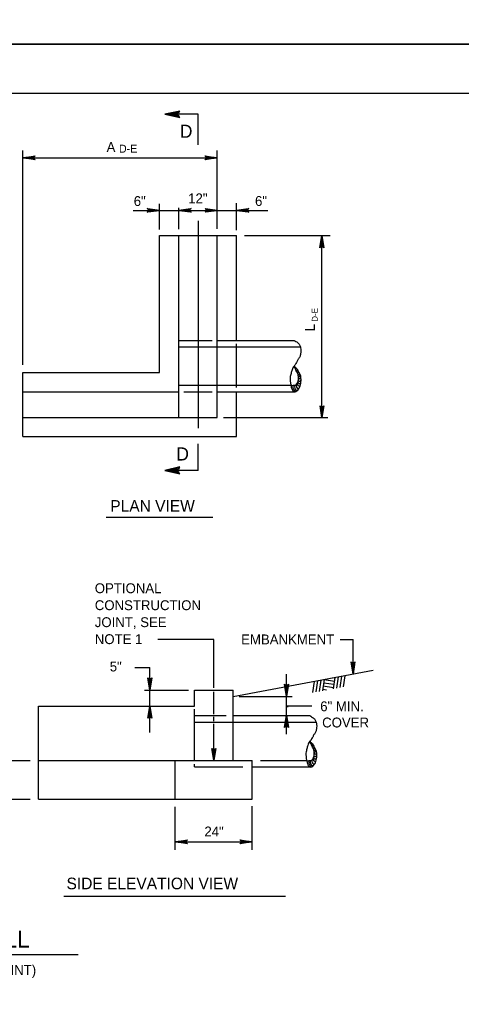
# Model space of a CAD drawing. Extents: x 638877 to 639960, y 297341 to 299123.
# Drawn here: x 639059.3 to 639193.8, y 298239.6 to 298536.8 of the extents above; entities that cross this region are included whole.
import ezdxf

# ---------------------------------------------------------------- set-up
doc = ezdxf.new("R2010")
doc.units = 0
for name, color, linetype in [('1', 7, 'Continuous'), ('2', 7, 'Continuous'), ('3', 7, 'Continuous'), ('PLT-BNDY', 7, 'Continuous')]:
    doc.layers.add(name, color=color, linetype=linetype)

msp = doc.modelspace()

# ---------------------------------------------------------------- linework, layer by layer
at = {"layer": '1'}
for p, q in [((639703.19, 298514.28), (638917.19, 298514.28)), ((639113.62, 298498.68), (639113.62, 298507.99)), ((639113.62, 298475.64), (639113.62, 298412.62)), ((639113.62, 298399.73), (639113.62, 298407.86)), ((639118.42, 298333.63), (639118.42, 298348.41)), ((639156.27, 298336.99), (639155.76, 298333.57)), ((639157.29, 298337.18), (639156.78, 298333.76)), ((639158.32, 298337.37), (639157.8, 298333.95)), ((639148.95, 298335.63), (639148.44, 298332.23)), ((639149.98, 298335.82), (639149.46, 298332.42)), ((639151, 298336.01), (639150.49, 298332.61)), ((639152.02, 298336.2), (639151.51, 298332.79)), ((639154.81, 298333.69), (639151.71, 298334.16)), ((639154.96, 298334.66), (639151.86, 298335.13)), ((639155.11, 298335.63), (639152.01, 298336.1)), ((639155.25, 298336.6), (639154.67, 298336.69)), ((639155.25, 298336.8), (639154.74, 298333.39)), ((639118.42, 298325.7), (639118.42, 298332.47)), ((639152.71, 298333.01), (639151.57, 298333.18)), ((639118.42, 298323.58), (639118.42, 298324.9)), ((639118.42, 298311.57), (639118.42, 298322.7))]:
    msp.add_line(p, q, dxfattribs=at)
at = {"layer": '2'}
for p, q in [((639113.62, 298507.99), (639103.48, 298507.99)), ((639060.32, 298431.85), (639060.32, 298496.98)), ((639060.32, 298494.76), (639119.47, 298494.76)), ((639119.47, 298473.15), (639119.47, 298496.98)), ((639101.92, 298472.96), (639101.92, 298480.79)), ((639125.32, 298472.81), (639125.32, 298480.94)), ((639093.88, 298478.8), (639107.77, 298478.8)), ((639107.77, 298473.1), (639107.77, 298479.57)), ((639107.77, 298478.8), (639119.47, 298478.8)), ((639119.47, 298478.8), (639134.9, 298478.8)), ((639101.92, 298429.54), (639101.92, 298471.14)), ((639101.92, 298471.14), (639125.32, 298471.14)), ((639107.77, 298415.89), (639107.77, 298471.14)), ((639119.47, 298415.89), (639119.47, 298471.14)), ((639125.32, 298439.29), (639125.32, 298471.14)), ((639127.8, 298471.14), (639153.78, 298471.14)), ((639151.32, 298415.89), (639151.32, 298471.14)), ((639107.77, 298439.29), (639117.93, 298439.29)), ((639119.47, 298439.29), (639142.87, 298439.29)), ((639125.32, 298424.96), (639125.32, 298438.2)), ((639107.77, 298437.34), (639144.61, 298437.34)), ((639060.32, 298429.54), (639101.92, 298429.54)), ((639060.32, 298410.04), (639060.32, 298429.54)), ((639060.32, 298423.69), (639107.77, 298423.69)), ((639107.77, 298425.64), (639141.85, 298425.64)), ((639109.32, 298423.69), (639117.93, 298423.69)), ((639119.47, 298423.69), (639142.87, 298423.69)), ((639125.32, 298410.04), (639125.32, 298423.69)), ((639060.32, 298415.89), (639119.47, 298415.89)), ((639121.37, 298415.89), (639153.12, 298415.89)), ((639060.32, 298410.04), (639125.32, 298410.04)), ((639113.62, 298399.73), (639103.48, 298399.73)), ((639118.42, 298348.41), (639101.37, 298348.41)), ((639156.86, 298348.41), (639160.78, 298348.41)), ((639160.78, 298337.86), (639160.78, 298348.41)), ((639094.44, 298339.9), (639098.96, 298339.9)), ((639098.96, 298328.14), (639098.96, 298339.9)), ((639124.27, 298331.07), (639166.89, 298339)), ((639140.55, 298331.07), (639140.55, 298337.83)), ((639097.37, 298333.02), (639110.72, 298333.02)), ((639112.57, 298333.02), (639124.27, 298333.02)), ((639112.57, 298328.14), (639112.57, 298333.02)), ((639124.27, 298311.57), (639124.27, 298333.02)), ((639126.16, 298331.07), (639142.22, 298331.07)), ((639140.55, 298325.35), (639140.55, 298331.07)), ((639065.12, 298299.87), (639065.12, 298328.14)), ((639065.12, 298328.14), (639112.57, 298328.14)), ((639098.96, 298320.15), (639098.96, 298328.14)), ((639140.55, 298328.21), (639148.24, 298328.21)), ((639112.57, 298311.57), (639112.57, 298327.18)), ((639112.57, 298325.22), (639122.17, 298325.22)), ((639124.27, 298325.22), (639147.67, 298325.22)), ((639140.55, 298319.63), (639140.55, 298325.35)), ((639112.57, 298323.27), (639149.41, 298323.27)), ((639010.52, 298311.57), (639062.52, 298311.57)), ((639065.12, 298311.57), (639130.12, 298311.57)), ((639106.72, 298299.87), (639106.72, 298311.57)), ((639112.57, 298309.62), (639112.57, 298310.5)), ((639130.12, 298299.87), (639130.12, 298311.57)), ((639132.63, 298311.57), (639146.65, 298311.57)), ((639112.57, 298309.62), (639127.28, 298309.62)), ((639130.12, 298309.62), (639147.67, 298309.62)), ((639010.52, 298299.87), (639062.52, 298299.87)), ((639065.12, 298299.87), (639130.12, 298299.87)), ((639106.72, 298284.49), (639106.72, 298297.48)), ((639130.12, 298284.49), (639130.12, 298297.76)), ((639106.72, 298286.88), (639130.12, 298286.88))]:
    msp.add_line(p, q, dxfattribs=at)
for points in [[(639107.84, 298508.72), (639107.68, 298508.3), (639103.48, 298507.99), (639107.84, 298508.72), (639108.06, 298508.97), (639103.48, 298507.99), (639107.67, 298507.71), (639107.83, 298507.3), (639103.48, 298507.99), (639108.06, 298507.02), (639107.83, 298507.3)], [(639063.86, 298494.32), (639063.73, 298494.57), (639060.32, 298494.76), (639063.86, 298494.32), (639064.04, 298494.16), (639060.32, 298494.76), (639063.73, 298494.93), (639063.85, 298495.18), (639060.32, 298494.76), (639064.04, 298495.35), (639063.85, 298495.18)], [(639115.93, 298495.21), (639116.06, 298494.95), (639119.47, 298494.76), (639115.93, 298495.21), (639115.75, 298495.36), (639119.47, 298494.76), (639116.06, 298494.59), (639115.94, 298494.34), (639119.47, 298494.76), (639115.75, 298494.17), (639115.94, 298494.34)], [(639098.38, 298479.25), (639098.51, 298478.99), (639101.92, 298478.8), (639098.38, 298479.25), (639098.2, 298479.4), (639101.92, 298478.8), (639098.51, 298478.63), (639098.39, 298478.38), (639101.92, 298478.8), (639098.2, 298478.21), (639098.39, 298478.38)], [(639111.31, 298478.36), (639111.18, 298478.62), (639107.77, 298478.8), (639111.31, 298478.36), (639111.49, 298478.2), (639107.77, 298478.8), (639111.18, 298478.97), (639111.3, 298479.22), (639107.77, 298478.8), (639111.49, 298479.4), (639111.3, 298479.22)], [(639115.93, 298479.25), (639116.06, 298478.99), (639119.47, 298478.8), (639115.93, 298479.25), (639115.75, 298479.4), (639119.47, 298478.8), (639116.06, 298478.63), (639115.94, 298478.38), (639119.47, 298478.8), (639115.75, 298478.21), (639115.94, 298478.38)], [(639128.86, 298478.36), (639128.73, 298478.62), (639125.32, 298478.8), (639128.86, 298478.36), (639129.04, 298478.2), (639125.32, 298478.8), (639128.73, 298478.97), (639128.85, 298479.22), (639125.32, 298478.8), (639129.04, 298479.4), (639128.85, 298479.22)], [(639150.88, 298467.6), (639151.13, 298467.74), (639151.32, 298471.14), (639150.88, 298467.6), (639150.72, 298467.42), (639151.32, 298471.14), (639151.49, 298467.74), (639151.74, 298467.61), (639151.32, 298471.14), (639151.91, 298467.42), (639151.74, 298467.61)], [(639151.74, 298419.2), (639151.5, 298419.08), (639151.32, 298415.89), (639151.74, 298419.2), (639151.88, 298419.37), (639151.32, 298415.89), (639151.16, 298419.07), (639150.93, 298419.19), (639151.32, 298415.89), (639150.77, 298419.37), (639150.93, 298419.19)], [(639107.84, 298400.54), (639107.68, 298400.08), (639103.48, 298399.73), (639107.84, 298400.54), (639108.06, 298400.81), (639103.48, 298399.73), (639107.67, 298399.43), (639107.83, 298398.98), (639103.48, 298399.73), (639108.06, 298398.67), (639107.83, 298398.98)], [(639161.23, 298341.4), (639160.97, 298341.27), (639160.78, 298337.86), (639161.23, 298341.4), (639161.38, 298341.58), (639160.78, 298337.86), (639160.61, 298341.26), (639160.36, 298341.39), (639160.78, 298337.86), (639160.19, 298341.58), (639160.36, 298341.39)], [(639099.41, 298336.56), (639099.15, 298336.42), (639098.96, 298333.02), (639099.41, 298336.56), (639099.56, 298336.74), (639098.96, 298333.02), (639098.79, 298336.42), (639098.54, 298336.55), (639098.96, 298333.02), (639098.37, 298336.74), (639098.54, 298336.55)], [(639141, 298334.61), (639140.74, 298334.47), (639140.55, 298331.07), (639141, 298334.61), (639141.15, 298334.79), (639140.55, 298331.07), (639140.38, 298334.47), (639140.13, 298334.6), (639140.55, 298331.07), (639139.96, 298334.79), (639140.13, 298334.6)], [(639098.52, 298324.6), (639098.78, 298324.73), (639098.96, 298328.14), (639098.52, 298324.6), (639098.36, 298324.41), (639098.96, 298328.14), (639099.13, 298324.73), (639099.38, 298324.61), (639098.96, 298328.14), (639099.56, 298324.41), (639099.38, 298324.61)], [(639140.11, 298321.81), (639140.36, 298321.94), (639140.55, 298325.35), (639140.11, 298321.81), (639139.95, 298321.62), (639140.55, 298325.35), (639140.72, 298321.94), (639140.97, 298321.82), (639140.55, 298325.35), (639141.14, 298321.62), (639140.97, 298321.82)], [(639118.86, 298315.11), (639118.61, 298314.97), (639118.42, 298311.57), (639118.86, 298315.11), (639119.02, 298315.29), (639118.42, 298311.57), (639118.25, 298314.97), (639118, 298315.1), (639118.42, 298311.57), (639117.83, 298315.29), (639118, 298315.1)], [(639110.26, 298286.44), (639110.13, 298286.7), (639106.72, 298286.88), (639110.26, 298286.44), (639110.44, 298286.28), (639106.72, 298286.88), (639110.13, 298287.05), (639110.25, 298287.3), (639106.72, 298286.88), (639110.44, 298287.48), (639110.25, 298287.3)], [(639126.58, 298287.33), (639126.71, 298287.07), (639130.12, 298286.88), (639126.58, 298287.33), (639126.4, 298287.48), (639130.12, 298286.88), (639126.71, 298286.71), (639126.59, 298286.46), (639130.12, 298286.88), (639126.4, 298286.29), (639126.59, 298286.46)]]:
    msp.add_lwpolyline(points, dxfattribs=at)
for centre, radius, start, end in [((639143.24, 298430.89), 0.127, 176.947, 93.053), ((639143.34, 298430.76), 0.298, 285.6074, 325.806), ((639143.73, 298430.14), 0.173, 195.7562, 33.8551), ((639144.06, 298429.61), 0.174, 203.3341, 43.8053), ((639144.32, 298429.03), 0.253, 188.5456, 52.8367), ((639144.49, 298426.08), 0.667, 173.2089, 278.5784), ((639144.45, 298426.57), 0.415, 171.0795, 335.4873), ((639144.39, 298428.53), 0.291, 223.7085, 2.3299), ((639144.57, 298427.23), 0.359, 199.7004, 348.5016), ((639144.52, 298427.95), 0.315, 212.411, 346.6825), ((639144.15, 298425.18), 1.67, 168.491, 237.5129), ((639144.14, 298425.16), 1.18, 158.8965, 245.9336), ((639144.64, 298425.54), 1.18, 164.8508, 242.5231), ((639148.04, 298316.81), 0.127, 176.947, 93.053), ((639148.14, 298316.68), 0.298, 285.6074, 325.806), ((639148.53, 298316.06), 0.173, 195.7562, 33.8551), ((639148.86, 298315.53), 0.174, 203.3341, 43.8053), ((639149.12, 298314.95), 0.253, 188.5456, 52.8367), ((639149.19, 298314.45), 0.291, 223.7085, 2.3299), ((639149.32, 298313.87), 0.315, 212.411, 346.6825), ((639148.95, 298311.1), 1.67, 168.491, 237.5129), ((639148.94, 298311.08), 1.18, 158.8965, 245.9336), ((639149.43, 298311.46), 1.18, 164.8508, 242.5231), ((639149.29, 298312), 0.667, 173.2089, 278.5784), ((639149.25, 298312.49), 0.415, 171.0795, 335.4873), ((639149.37, 298313.15), 0.359, 199.7004, 348.5016)]:
    msp.add_arc(centre, radius, start, end, dxfattribs=at)
for points in [[(639142.87, 298439.29), (639143.37, 298438.95), (639143.9, 298438.62), (639144.47, 298437.97), (639144.83, 298437.02), (639144.85, 298435.23), (639144.57, 298434.26), (639144.11, 298433.54), (639143.71, 298432.78), (639143.4, 298432.26), (639143.14, 298431.8), (639142.87, 298431.49), (639142.47, 298430.9), (639142.23, 298430.28), (639141.92, 298429.26), (639141.78, 298428.64), (639141.66, 298427.9), (639141.66, 298427.35), (639141.73, 298426.42), (639141.92, 298425.44), (639142.09, 298424.73), (639142.45, 298423.99), (639142.87, 298423.69), (639143.42, 298423.73), (639143.95, 298424.18), (639144.38, 298424.71), (639144.66, 298425.32), (639144.9, 298426.14), (639144.97, 298427.11), (639144.95, 298427.92), (639144.69, 298428.92), (639144.3, 298429.66), (639143.95, 298430.33), (639143.49, 298430.85), (639142.87, 298431.49)], [(639141.85, 298425.64), (639142.33, 298425.61), (639142.95, 298425.66), (639143.28, 298425.71), (639143.54, 298425.95), (639143.73, 298426.14), (639143.92, 298426.44), (639144.07, 298426.87), (639144.16, 298427.33), (639144.18, 298427.83), (639144.18, 298428.25), (639144.09, 298428.71), (639143.99, 298429.14), (639143.83, 298429.44), (639143.52, 298429.99), (639143.42, 298430.26), (639143.33, 298430.49), (639143.07, 298430.9), (639142.95, 298431.18), (639142.87, 298431.49)], [(639147.67, 298325.22), (639148.17, 298324.87), (639148.7, 298324.54), (639149.27, 298323.89), (639149.63, 298322.94), (639149.65, 298321.15), (639149.36, 298320.18), (639148.91, 298319.46), (639148.51, 298318.7), (639148.2, 298318.18), (639147.93, 298317.72), (639147.67, 298317.42), (639147.27, 298316.82), (639147.03, 298316.2), (639146.72, 298315.18), (639146.58, 298314.56), (639146.46, 298313.82), (639146.46, 298313.27), (639146.53, 298312.34), (639146.72, 298311.36), (639146.89, 298310.65), (639147.25, 298309.91), (639147.67, 298309.62), (639148.22, 298309.65), (639148.75, 298310.1), (639149.17, 298310.63), (639149.46, 298311.25), (639149.7, 298312.06), (639149.77, 298313.03), (639149.74, 298313.84), (639149.48, 298314.84), (639149.1, 298315.58), (639148.75, 298316.25), (639148.29, 298316.77), (639147.67, 298317.42)], [(639146.65, 298311.57), (639147.13, 298311.53), (639147.74, 298311.58), (639148.08, 298311.63), (639148.34, 298311.87), (639148.53, 298312.06), (639148.72, 298312.37), (639148.87, 298312.79), (639148.96, 298313.25), (639148.98, 298313.75), (639148.98, 298314.18), (639148.89, 298314.63), (639148.79, 298315.06), (639148.63, 298315.37), (639148.32, 298315.91), (639148.22, 298316.18), (639148.13, 298316.41), (639147.86, 298316.82), (639147.74, 298317.11), (639147.67, 298317.42)]]:
    msp.add_spline(points, degree=3, dxfattribs=at)
at = {"layer": '3'}
for p, q in [((639085.72, 298385.54), (639118.13, 298385.54)), ((639072.83, 298270.38), (639140.19, 298270.38)), ((638994.2, 298252.63), (639077.11, 298252.63))]:
    msp.add_line(p, q, dxfattribs=at)
at = {"layer": 'PLT-BNDY'}
for points in [[(638877.19, 299123.28), (639718.19, 299123.28), (639718.19, 298529.28), (638877.19, 298529.28)], [(638877.19, 298529.28), (639718.19, 298529.28), (639718.19, 297935.28), (638877.19, 297935.28)]]:
    msp.add_lwpolyline(points, close=True, dxfattribs=at)

# ---------------------------------------------------------------- texts
at = {"layer": '1'}
msp.add_text('D-E', height=2.43, dxfattribs=at).set_placement((639089.57, 298496.32))
msp.add_text('D-E', height=1.8, rotation=90, dxfattribs=at).set_placement((639150.05, 298444.95))
at = {"layer": '2'}
msp.add_text('L', height=3, rotation=90, dxfattribs=at).set_placement((639149.17, 298442.05))
msp.add_text('.', height=3.9, dxfattribs=at).set_placement((639140.16, 298327.79))
at = {"layer": '3'}
for s, height, p in [('D', 3.99, (639108.07, 298500.84)), ('A', 3, (639085.81, 298496.53)), ('6"', 3, (639094.07, 298480.11)), ('12"', 3, (639110.63, 298480.94)), ('6"', 3, (639130.97, 298480.14)), ('D', 3.99, (639107, 298402.77)), ('PLAN VIEW', 3.53, (639086.94, 298387.19)), ('OPTIONAL', 3, (639082.22, 298362.45)), ('CONSTRUCTION ', 2.9999, (639082.22, 298357.29)), ('JOINT, SEE', 3, (639082.22, 298352.13)), ('NOTE 1', 3, (639082.22, 298346.97)), ('EMBANKMENT', 3, (639126.75, 298346.89)), ('5"', 3, (639086.77, 298338.66)), ('6" MIN.', 3, (639150.8, 298326.56)), ('COVER', 3, (639151.39, 298321.64)), ('24"', 3, (639115.57, 298288.52)), ('SIDE ELEVATION VIEW', 3.5299, (639073.62, 298272.46)), ('TYPE D-E ENDWALL', 5.1858, (638995, 298254.74)), ('(WITH OPTIONAL CONSTRUCTION JOINT)', 2.9999, (638983.93, 298246.42))]:
    msp.add_text(s, height=height, dxfattribs=at).set_placement(p)

doc.saveas('drawing.dxf')
